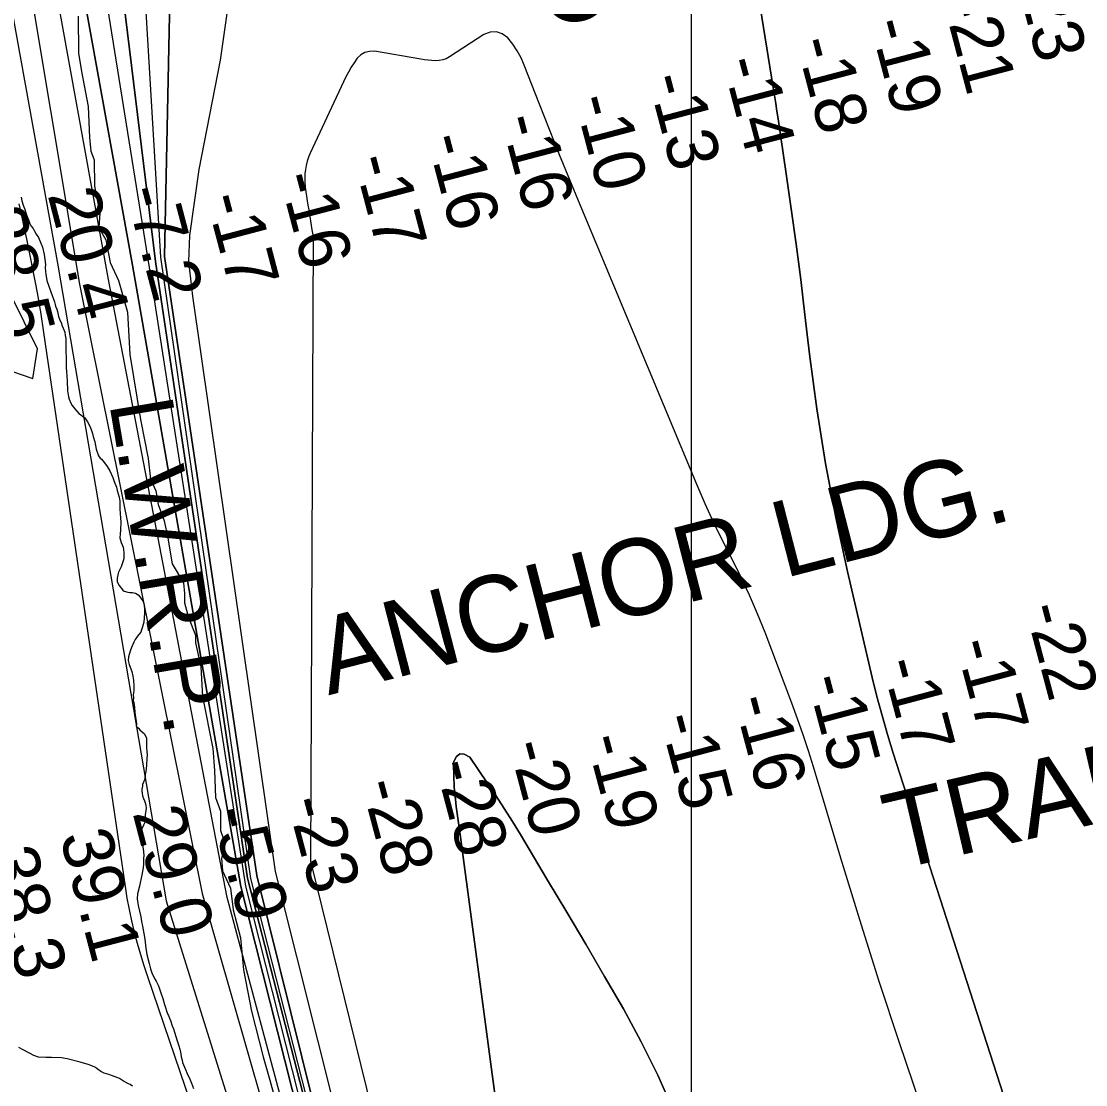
# Model space of a CAD drawing. Extents: x 3250478 to 3288318, y 788638 to 816472.
# Drawn here: x 3274716 to 3276111, y 797415 to 798809 of the extents above; entities that cross this region are included whole.
import ezdxf

# ---------------------------------------------------------------- set-up
doc = ezdxf.new("R2010")
doc.units = 0
for name, color, linetype in [('V-BORW-LINE', 7, 'Continuous'), ('V-CHAN-NAID', 7, 'Continuous'), ('V-GRID-MAJR', 7, 'Continuous'), ('V-RIVR-EDGE', 7, 'Continuous'), ('V-RIVR-RANG', 7, 'Continuous'), ('V-SITE-VEGE', 7, 'Continuous'), ('V-TOPO-DPTH', 7, 'Continuous'), ('V-TOPO-GNAM-IDEN', 7, 'Continuous'), ('V-TOPO-MAJR', 7, 'Continuous'), ('V-TOPO-MINR', 7, 'Continuous'), ('V-TOPO-WATR', 7, 'Continuous'), ('V-TOPO-WATR-IDEN', 7, 'Continuous')]:
    doc.layers.add(name, color=color, linetype=linetype)

msp = doc.modelspace()

# ---------------------------------------------------------------- linework, layer by layer
at = {"layer": 'V-BORW-LINE'}
msp.add_lwpolyline([(3274703.2, 798350.4), (3274731.2, 798340.9), (3274737.2, 798379.6), (3274702.3, 798450.3)], dxfattribs=at)
at = {"layer": 'V-GRID-MAJR'}
msp.add_spline([(3275593.9, 794016.6), (3275594.8, 800075.6), (3275595.7, 806137.8), (3275596.6, 812200), (3275596.6, 812203)], degree=3, dxfattribs=at)
at = {"layer": 'V-RIVR-EDGE'}
msp.add_lwpolyline([(3274790.4, 798816.1), (3274791.1, 798767.4), (3274795, 798743.5), (3274803.5, 798697.4), (3274805.2, 798656.9), (3274806.9, 798638.7), (3274811.6, 798627.4), (3274812, 798593), (3274818.8, 798557.4), (3274817.5, 798538.7), (3274826.6, 798522.6), (3274832.2, 798493), (3274843.4, 798469.1), (3274855, 798427.7), (3274858.4, 798372.1), (3274872.1, 798286.9), (3274882.4, 798236), (3274885.4, 798208.6), (3274892.3, 798193.4), (3274895.3, 798175.5), (3274903, 798154.2), (3274908.2, 798131.6), (3274913.8, 798097.7), (3274928.5, 798072.9), (3274929.8, 798058.9), (3274929.7, 798046.8), (3274935.3, 798027.2), (3274944.4, 798004.1), (3274944.4, 797994.1), (3274951.2, 797962.8), (3274953.3, 797923.7), (3274967.1, 797855.4), (3274969.2, 797826.7), (3274970.4, 797791.1), (3274976.9, 797773.2), (3274977.2, 797748), (3274983.3, 797730.6), (3274978.4, 797711.9), (3274979.7, 797695), (3274990.1, 797672.4), (3274993.5, 797644.1), (3275003.4, 797607.1), (3275007.2, 797565.4), (3275017.5, 797511), (3275033, 797451.4), (3275041.6, 797420.6), (3275047.7, 797398.4)], dxfattribs=at)
at = {"layer": 'V-SITE-VEGE'}
for points in [[(3274715.9, 798578.5), (3274716.6, 798574), (3274718.3, 798568.2), (3274720, 798563.7), (3274722.3, 798556.7), (3274724, 798551.8), (3274725.3, 798548.8), (3274726.7, 798544.9), (3274728.9, 798540.7), (3274731.5, 798537.4), (3274732.8, 798534.7), (3274735.4, 798530.2), (3274738.3, 798525.6)], [(3274738.3, 798525.6), (3274741.5, 798518.4), (3274743.8, 798513), (3274746, 798503.2), (3274747.6, 798490.4), (3274747.4, 798486.4), (3274747.5, 798481.3), (3274748, 798477.6), (3274749.4, 798469.4), (3274754.5, 798454.5), (3274759.5, 798441.2), (3274760.2, 798437.9), (3274760.8, 798435.8), (3274762.5, 798431.8), (3274763.5, 798428.5), (3274764.6, 798422.1), (3274765.9, 798418.5), (3274768.6, 798413), (3274769.2, 798410.6), (3274770.6, 798407), (3274773.2, 798401.6), (3274773.6, 798397.3), (3274774.4, 798393.3), (3274774.1, 798380.2), (3274774.6, 798364.6), (3274774.6, 798355.1), (3274775.1, 798349.6), (3274775.8, 798344.1), (3274776, 798337.1), (3274776.4, 798324.8), (3274777.1, 798321.8), (3274777.6, 798316.9), (3274778.6, 798313.6), (3274780.9, 798308.5), (3274782.8, 798305.5), (3274786.3, 798301), (3274791.4, 798295), (3274793.6, 798293.8), (3274796.7, 798290.9), (3274799.2, 798289.1), (3274802.7, 798284), (3274805.9, 798278.3), (3274807.6, 798274.1), (3274809.3, 798268.6), (3274810.3, 798264.7), (3274812.1, 798257.7), (3274813.1, 798252.8), (3274814.2, 798248.3), (3274817.2, 798239.5), (3274819.4, 798236.5), (3274821, 798235), (3274823.6, 798232), (3274828.3, 798225.4), (3274831.9, 798219.7), (3274835.8, 798211), (3274837.8, 798205.8), (3274840.5, 798198.3), (3274841.5, 798193.7), (3274844.2, 798185.2), (3274845, 798180), (3274845.3, 798169.3), (3274845.5, 798164.1), (3274846, 798157.4), (3274846.4, 798153.2), (3274845.8, 798142.1), (3274845.4, 798137.2), (3274845.2, 798132), (3274846.9, 798125.9), (3274849.3, 798119.6), (3274850.4, 798112.6), (3274850.5, 798108.9), (3274850.3, 798104.9), (3274849.5, 798101.5), (3274846.7, 798093.8), (3274843.5, 798087), (3274842.4, 798083.3), (3274841.6, 798079), (3274841.7, 798074.4), (3274842.4, 798072.3), (3274844, 798069.5), (3274848.8, 798063), (3274850.7, 798061.8), (3274855.6, 798060.7), (3274858.1, 798060.2), (3274861.5, 798060), (3274863.6, 798059.7), (3274865.8, 798059.2), (3274868.9, 798057.1), (3274871.7, 798054.2), (3274875.6, 798048.2), (3274876.9, 798043.9), (3274877.4, 798037.2), (3274877.6, 798032.9), (3274876.4, 798021.3), (3274875.6, 798018.2), (3274874.7, 798015.1), (3274873.6, 798011.4), (3274872.5, 798008.3), (3274870.1, 798004.9), (3274868.1, 798003), (3274865.4, 797998.6)], [(3274865.4, 797998.6), (3274863.4, 797994.9), (3274860.2, 797988), (3274858.6, 797983.1), (3274856.3, 797975.7), (3274856.2, 797971.1), (3274857.2, 797965.9), (3274860.6, 797956.5), (3274862.3, 797950.5), (3274862.8, 797944.7), (3274863.3, 797937.9), (3274863.5, 797931.2), (3274862.7, 797926), (3274862.8, 797922.3), (3274862.6, 797918.3), (3274863.6, 797915.9), (3274864.4, 797909.2), (3274864.9, 797902.8), (3274866.9, 797887.9), (3274866.7, 797884.8), (3274869.5, 797882.1), (3274871.4, 797880.1), (3274874.6, 797877.1), (3274877.4, 797875), (3274880, 797869), (3274880.2, 797864.4), (3274880.1, 797856.8), (3274880.6, 797851.6), (3274880.7, 797847), (3274880.5, 797842.4), (3274879.9, 797833.8), (3274879.7, 797828.9), (3274879.2, 797825.5), (3274878.4, 797821.5), (3274878, 797815.4), (3274874.8, 797808.2), (3274874.6, 797806.1), (3274873.8, 797802.4), (3274874.1, 797800), (3274874.2, 797796.9), (3274875, 797793.3), (3274876, 797789.9), (3274877.3, 797786.9), (3274878.9, 797783), (3274879.3, 797780.8), (3274879.4, 797777.5), (3274879.2, 797774.1), (3274878.5, 797768.6), (3274878.3, 797764), (3274878.4, 797759.4), (3274876.1, 797755), (3274874.7, 797751.9), (3274872.6, 797748.2), (3274873.4, 797743.9), (3274873.5, 797740), (3274874.7, 797729.6), (3274875.4, 797726.6), (3274876.2, 797720.5), (3274876.4, 797715), (3274876.2, 797711.9), (3274876.1, 797704.6), (3274875.6, 797699), (3274874.1, 797690.1), (3274870.9, 797675), (3274868.4, 797665.2), (3274868, 797658.4), (3274868.9, 797649.6), (3274872.7, 797635), (3274873.5, 797628.9), (3274874.6, 797622.8), (3274876.4, 797612.8), (3274877.8, 797605.5), (3274879.1, 797593.9), (3274880.3, 797585.4), (3274883.4, 797573.8), (3274885.4, 797566.5), (3274887.1, 797561.4), (3274890.4, 797554.1), (3274892.6, 797550.5), (3274895.2, 797545.4), (3274896.6, 797541.8), (3274899.3, 797533.9), (3274901.6, 797527.6), (3274903.7, 797520), (3274907.7, 797507.5), (3274909, 797505.4), (3274910, 797502.1), (3274911.3, 797498.8), (3274913.7, 797491.8), (3274915.3, 797487.9), (3274916.7, 797483.6), (3274920.4, 797472.4), (3274922.4, 797465.5), (3274923.8, 797461.2), (3274925.2, 797455.1), (3274925.6, 797451.2), (3274926.7, 797446.9), (3274927.1, 797443.9), (3274930, 797437.8), (3274931, 797434.8), (3274933.3, 797429.4)], [(3274861.6, 797412.8), (3274858.5, 797414.9), (3274856.6, 797415.7), (3274850.1, 797419.2), (3274844.8, 797422.7), (3274842.3, 797423.6), (3274835.5, 797426.4), (3274830.5, 797428.1), (3274824.4, 797429.8), (3274820.3, 797431.8), (3274815.3, 797435.3), (3274813.4, 797437.1), (3274808.2, 797439.4), (3274803.5, 797441.1), (3274793.3, 797444.4), (3274776.1, 797448.5), (3274768.7, 797449.8), (3274755.5, 797450.3), (3274748.2, 797450.4), (3274738.4, 797450.8), (3274732.5, 797453), (3274726.6, 797455.9), (3274717.6, 797460.8), (3274712.9, 797463.5)], [(3274933.3, 797429.4), (3274937.2, 797420.9), (3274938.9, 797416.7), (3274941.8, 797409.7)]]:
    msp.add_lwpolyline(points, dxfattribs=at)
at = {"layer": 'V-TOPO-DPTH'}
for points in [[(3275320.7, 796729.2), (3275299.6, 796772.4), (3275248, 796842.5), (3275216.1, 796884.8), (3275081.1, 797418.9), (3275012.4, 797685.4), (3274892, 798494.3), (3274803.2, 799219.5)], [(3274803.2, 799219.5), (3274892, 798494.3), (3275012.4, 797685.4), (3275081.1, 797418.9), (3275216.1, 796884.8), (3275248, 796842.5), (3275299.6, 796772.4), (3275320.7, 796729.2)], [(3275360.9, 796759.7), (3275343.1, 796787), (3275321.3, 796804.6), (3275285.9, 796832.9), (3275225.3, 796888.9), (3275221.2, 796893.6), (3275201.7, 796975.5), (3275024.8, 797689.1), (3274903.6, 798500.7), (3274917.8, 799176.2)], [(3274917.8, 799176.2), (3274903.6, 798500.7), (3275024.8, 797689.1), (3275201.7, 796975.5), (3275221.2, 796893.6), (3275225.3, 796888.9), (3275285.9, 796832.9), (3275321.3, 796804.6), (3275343.1, 796787), (3275360.9, 796759.7)], [(3275629.2, 799170.6), (3275701.6, 798722.2), (3275703.3, 798711.9), (3275704.9, 798701.6), (3275706.5, 798691.4), (3275708, 798681.1), (3275718.7, 798609.3), (3275725.3, 798563.1), (3275731.7, 798516.8), (3275737.6, 798470.5), (3275743.2, 798424.2), (3275749.1, 798372.8), (3275758.7, 798301), (3275769.9, 798229.4), (3275783.6, 798158.3), (3275798.9, 798087.5), (3275831.4, 797948.6), (3275837.6, 797923.6), (3275844.2, 797898.7), (3275851.4, 797874), (3275859, 797849.4), (3276091.2, 797128.7)], [(3276091.2, 797128.7), (3275859, 797849.4), (3275851.4, 797874), (3275844.2, 797898.7), (3275837.6, 797923.6), (3275831.4, 797948.6), (3275798.9, 798087.5), (3275783.6, 798158.3), (3275769.9, 798229.4), (3275758.7, 798301), (3275749.1, 798372.8), (3275743.2, 798424.2), (3275737.6, 798470.5), (3275731.7, 798516.8), (3275725.3, 798563.1), (3275718.7, 798609.3), (3275708, 798681.1), (3275706.5, 798691.4), (3275704.9, 798701.6), (3275703.3, 798711.9), (3275701.6, 798722.2), (3275629.2, 799170.6)], [(3275270.1, 796729.6), (3275205.7, 796875.8), (3275003.6, 797674.8), (3274861.6, 798489.6), (3274742.1, 799152.7)], [(3275894.3, 797389.7), (3275867, 797469.8), (3275840.4, 797550.1), (3275814.9, 797630.8), (3275790.1, 797711.7), (3275754.3, 797831.5), (3275747.8, 797852.6), (3275740.9, 797873.6), (3275733.6, 797894.4), (3275726, 797915.2), (3275691, 798007.6), (3275681.1, 798032.3), (3275670.6, 798056.7), (3275659.2, 798080.8), (3275647.2, 798104.6), (3275635.2, 798128.3), (3275623.5, 798152.3), (3275612.5, 798176.5), (3275601.9, 798200.9), (3275448.4, 798568.5), (3275434.8, 798601.4), (3275421.4, 798634.3), (3275408.2, 798667.3), (3275395.2, 798700.4), (3275375.3, 798751.8), (3275371, 798761.4), (3275366, 798770.6), (3275360.2, 798779.2), (3275353.7, 798787.5), (3275346.4, 798792.7), (3275338.8, 798795.6), (3275330.6, 798794.9), (3275322.2, 798791.9), (3275277.1, 798762.5), (3275272.9, 798760.2), (3275268.5, 798758.6), (3275263.8, 798757.7), (3275259, 798757.4), (3275254.1, 798757.7), (3275249.2, 798758.1), (3275244.3, 798758.7), (3275239.5, 798759.5), (3275179, 798769.9), (3275172.4, 798769.8), (3275166.3, 798768.5), (3275161, 798765.3), (3275156.2, 798760.8), (3275152.1, 798754.9), (3275148.2, 798748.9), (3275144.7, 798742.6), (3275141.5, 798736.2), (3275094.6, 798636.1), (3275092.4, 798630.9), (3275090.6, 798625.7), (3275089.3, 798620.2), (3275088.3, 798614.7), (3275087.7, 798609.1), (3275087.5, 798603.6), (3275087.7, 798598), (3275088.1, 798592.4), (3275088.2, 798591.6), (3275089, 798585.7), (3275089.8, 798579.7), (3275090.7, 798573.8), (3275091.7, 798567.9), (3275092.7, 798562.1), (3275094.1, 798553.3), (3275095.5, 798544.5), (3275096.9, 798535.7), (3275098.3, 798526.9), (3275095.1, 797707.7), (3275263.8, 797023)], [(3275894.3, 797389.7), (3275867, 797469.8), (3275840.4, 797550.1), (3275814.9, 797630.8), (3275790.1, 797711.7), (3275754.3, 797831.5), (3275747.8, 797852.6), (3275740.9, 797873.6), (3275733.6, 797894.4), (3275726, 797915.2), (3275691, 798007.6), (3275681.1, 798032.3), (3275670.6, 798056.7), (3275659.2, 798080.8), (3275647.2, 798104.6), (3275635.2, 798128.3), (3275623.5, 798152.3), (3275612.5, 798176.5), (3275601.9, 798200.9), (3275448.4, 798568.5), (3275434.8, 798601.4), (3275421.4, 798634.3), (3275408.2, 798667.3), (3275395.2, 798700.4), (3275375.3, 798751.8), (3275371, 798761.4), (3275366, 798770.6), (3275360.2, 798779.2), (3275353.7, 798787.5), (3275346.4, 798792.7), (3275338.8, 798795.6), (3275330.6, 798794.9), (3275322.2, 798791.9), (3275277.1, 798762.5), (3275272.9, 798760.2), (3275268.5, 798758.6), (3275263.8, 798757.7), (3275259, 798757.4), (3275254.1, 798757.7), (3275249.2, 798758.1), (3275244.3, 798758.7), (3275239.5, 798759.5), (3275179, 798769.9), (3275172.4, 798769.8), (3275166.3, 798768.5), (3275161, 798765.3), (3275156.2, 798760.8), (3275152.1, 798754.9), (3275148.2, 798748.9), (3275144.7, 798742.6), (3275141.5, 798736.2), (3275094.6, 798636.1), (3275092.4, 798630.9), (3275090.6, 798625.7), (3275089.3, 798620.2), (3275088.3, 798614.7), (3275087.7, 798609.1), (3275087.5, 798603.6), (3275087.7, 798598), (3275088.1, 798592.4), (3275088.2, 798591.6), (3275089, 798585.7), (3275089.8, 798579.7), (3275090.7, 798573.8), (3275091.7, 798567.9), (3275092.7, 798562.1), (3275094.1, 798553.3), (3275095.5, 798544.5), (3275096.9, 798535.7), (3275098.3, 798526.9), (3275095.1, 797707.7), (3275263.8, 797023)], [(3275392.5, 796983.5), (3275291.2, 797742.6), (3275289.9, 797751.9), (3275288.7, 797761.2), (3275287.4, 797770.4), (3275286.1, 797779.7), (3275285, 797789), (3275284, 797798.3), (3275283.4, 797807.6), (3275283.1, 797816.9), (3275282.6, 797837.4), (3275286.1, 797844.6), (3275290.6, 797848.7), (3275296.6, 797848), (3275303.7, 797844.2), (3275326.8, 797810.5), (3275338, 797793.8), (3275348.9, 797777), (3275359.6, 797760), (3275370.1, 797742.9), (3275405.9, 797683.1), (3275431, 797641), (3275455.9, 797598.8), (3275480.6, 797556.5), (3275505.1, 797514), (3275528.4, 797471), (3275550.2, 797427.3), (3275569.9, 797382.5)], [(3275569.9, 797382.5), (3275550.2, 797427.3), (3275528.4, 797471), (3275505.1, 797514), (3275480.6, 797556.5), (3275455.9, 797598.8), (3275431, 797641), (3275405.9, 797683.1), (3275370.1, 797742.9), (3275359.6, 797760), (3275348.9, 797777), (3275338, 797793.8), (3275326.8, 797810.5), (3275303.7, 797844.2), (3275296.6, 797848), (3275290.6, 797848.7), (3275286.1, 797844.6), (3275282.6, 797837.4), (3275283.1, 797816.9), (3275283.4, 797807.6), (3275284, 797798.3), (3275285, 797789), (3275286.1, 797779.7), (3275287.4, 797770.4), (3275288.7, 797761.2), (3275289.9, 797751.9), (3275291.2, 797742.6), (3275392.5, 796983.5)]]:
    msp.add_lwpolyline(points, dxfattribs=at)
at = {"layer": 'V-TOPO-MAJR'}
msp.add_lwpolyline([(3274650.9, 799170.7), (3274703.8, 798821.2), (3274763.8, 798489.6), (3274905.8, 797655.9), (3275202.8, 796703.7)], dxfattribs=at)
at = {"layer": 'V-TOPO-MINR'}
for points in [[(3274856, 799209.7), (3274898.3, 798500), (3275016.3, 797685.3), (3275218.2, 796893), (3275224.1, 796883.6), (3275258.3, 796844.7), (3275285.9, 796815.8), (3275312.4, 796792.3), (3275324.8, 796774), (3275331.3, 796763.4), (3275338.4, 796751.6)], [(3275360.9, 796759.7), (3275343.1, 796787), (3275321.3, 796804.6), (3275285.9, 796832.9), (3275225.3, 796888.9), (3275221.2, 796893.6), (3275201.7, 796975.5), (3275024.8, 797689.1), (3274903.6, 798500.7), (3274917.8, 799176.2)], [(3275036.8, 799181.6), (3274976.4, 798758.3), (3274948.6, 798615), (3274936.2, 798528.3), (3274935.2, 798494.3), (3274940.4, 798448.9), (3275048.6, 797694.4), (3275243, 796919.1), (3275255.6, 796897.5), (3275289.9, 796868.6), (3275320.5, 796843.3), (3275354.8, 796816.3), (3275372.8, 796789.2), (3275383.7, 796766.6)], [(3274775.8, 799159.5), (3274883.7, 798486.4), (3275010, 797674.9), (3275210.9, 796880.7), (3275298.1, 796721.6)], [(3275629.2, 799170.6), (3275701.6, 798722.2), (3275703.3, 798711.9), (3275704.9, 798701.6), (3275706.5, 798691.4), (3275708, 798681.1), (3275718.7, 798609.3), (3275725.3, 798563.1), (3275731.7, 798516.8), (3275737.6, 798470.5), (3275743.2, 798424.2), (3275749.1, 798372.8), (3275758.7, 798301), (3275769.9, 798229.4), (3275783.6, 798158.3), (3275798.9, 798087.5), (3275831.4, 797948.6), (3275837.6, 797923.6), (3275844.2, 797898.7), (3275851.4, 797874), (3275859, 797849.4), (3276091.2, 797128.7)], [(3274678, 799145.7), (3274792.2, 798464.3), (3274953.1, 797665.3), (3275230, 796698.5)], [(3274706.5, 799151.5), (3274830, 798470.6), (3274984.7, 797662.2), (3275196.2, 796872.7), (3275244.9, 796729.1)], [(3274742.1, 799152.7), (3274861.6, 798489.6), (3275003.6, 797674.8), (3275205.7, 796875.8), (3275270.1, 796729.6)], [(3275894.3, 797389.7), (3275867, 797469.8), (3275840.4, 797550.1), (3275814.9, 797630.8), (3275790.1, 797711.7), (3275754.3, 797831.5), (3275747.8, 797852.6), (3275740.9, 797873.6), (3275733.6, 797894.4), (3275726, 797915.2), (3275691, 798007.6), (3275681.1, 798032.3), (3275670.6, 798056.7), (3275659.2, 798080.8), (3275647.2, 798104.6), (3275635.2, 798128.3), (3275623.5, 798152.3), (3275612.5, 798176.5), (3275601.9, 798200.9), (3275448.4, 798568.5), (3275434.8, 798601.4), (3275421.4, 798634.3), (3275408.2, 798667.3), (3275395.2, 798700.4), (3275375.3, 798751.8), (3275371, 798761.4), (3275366, 798770.6), (3275360.2, 798779.2), (3275353.7, 798787.5), (3275346.4, 798792.7), (3275338.8, 798795.6), (3275330.6, 798794.9), (3275322.2, 798791.9), (3275277.1, 798762.5), (3275272.9, 798760.2), (3275268.5, 798758.6), (3275263.8, 798757.7), (3275259, 798757.4), (3275254.1, 798757.7), (3275249.2, 798758.1), (3275244.3, 798758.7), (3275239.5, 798759.5), (3275179, 798769.9), (3275172.4, 798769.8), (3275166.3, 798768.5), (3275161, 798765.3), (3275156.2, 798760.8), (3275152.1, 798754.9), (3275148.2, 798748.9), (3275144.7, 798742.6), (3275141.5, 798736.2), (3275094.6, 798636.1), (3275092.4, 798630.9), (3275090.6, 798625.7), (3275089.3, 798620.2), (3275088.3, 798614.7), (3275087.7, 798609.1), (3275087.5, 798603.6), (3275087.7, 798598), (3275088.1, 798592.4), (3275088.2, 798591.6), (3275089, 798585.7), (3275089.8, 798579.7), (3275090.7, 798573.8), (3275091.7, 798567.9), (3275092.7, 798562.1), (3275094.1, 798553.3), (3275095.5, 798544.5), (3275096.9, 798535.7), (3275098.3, 798526.9), (3275095.1, 797707.7), (3275263.8, 797023)], [(3274712.7, 798570), (3274716.1, 798554.6), (3274719.4, 798539.3), (3274722.6, 798523.9), (3274725.7, 798508.6), (3274732.8, 798473.3), (3274734.6, 798464.4), (3274736.3, 798455.4), (3274737.9, 798446.3), (3274739.5, 798437.3), (3274741, 798428.3), (3274742.5, 798419.2), (3274743.9, 798410.2), (3274745.2, 798401.1), (3274851.9, 797674.5), (3274854.3, 797659.5), (3274857.1, 797644.5), (3274860.3, 797629.6), (3274863.9, 797614.8), (3274867.9, 797600.1), (3274872.1, 797585.4), (3274876.6, 797570.9), (3274881.3, 797556.4), (3275015.7, 797162.4)], [(3275569.9, 797382.5), (3275550.2, 797427.3), (3275528.4, 797471), (3275505.1, 797514), (3275480.6, 797556.5), (3275455.9, 797598.8), (3275431, 797641), (3275405.9, 797683.1), (3275370.1, 797742.9), (3275359.6, 797760), (3275348.9, 797777), (3275338, 797793.8), (3275326.8, 797810.5), (3275303.7, 797844.2), (3275296.6, 797848), (3275290.6, 797848.7), (3275286.1, 797844.6), (3275282.6, 797837.4), (3275283.1, 797816.9), (3275283.4, 797807.6), (3275284, 797798.3), (3275285, 797789), (3275286.1, 797779.7), (3275287.4, 797770.4), (3275288.7, 797761.2), (3275289.9, 797751.9), (3275291.2, 797742.6), (3275392.5, 796983.5)]]:
    msp.add_lwpolyline(points, dxfattribs=at)
at = {"layer": 'V-TOPO-WATR'}
msp.add_lwpolyline([(3275320.7, 796729.2), (3275299.6, 796772.4), (3275248, 796842.5), (3275216.1, 796884.8), (3275081.1, 797418.9), (3275012.4, 797685.4), (3274892, 798494.3), (3274803.2, 799219.5)], dxfattribs=at)

# ---------------------------------------------------------------- texts
at = {"layer": 'V-CHAN-NAID'}
for s, rotation, p in [('CROWN VANTAGE OUTFLOW (260.1)', 13.712, (3275402.3, 798798.9)), ('TRANSMONTAIGNE (259.9) (2)', 13.0616, (3275861.2, 797695.7))]:
    msp.add_text(s, height=100, rotation=rotation, dxfattribs=at).set_placement(p)
at = {"layer": 'V-RIVR-RANG'}
for s, rotation, p in [('-23', 284.7584, (3276016.3, 798876.9)), ('-21', 284.7584, (3275923.9, 798835.1)), ('-19', 284.7584, (3275828, 798806.8)), ('-18', 284.7584, (3275731, 798782.3)), ('-14', 284.7584, (3275634.4, 798756.3)), ('-13', 284.7584, (3275536.8, 798734.4)), ('-10', 284.7584, (3275440.6, 798706.8)), ('-16', 284.7584, (3275344.1, 798680.8)), ('-16', 284.7584, (3275247.3, 798655.6)), ('-17', 284.7584, (3275151.2, 798628.1)), ('-16', 284.7584, (3275053.8, 798605.1)), ('20.4', 284.4783, (3274750.2, 798582)), ('-7.2', 284.7584, (3274851.7, 798587.3)), ('-17', 284.7584, (3274957.6, 798577.6)), ('38.5', 284.4783, (3274653.5, 798556.8)), ('-22', 284.8695, (3276031.2, 798039.9)), ('-17', 284.8695, (3275940.1, 797993.3)), ('-17', 284.8695, (3275843.4, 797967.9)), ('-15', 284.8695, (3275745.7, 797946.3)), ('-16', 284.8695, (3275649.4, 797919.3)), ('-15', 284.8695, (3275552.3, 797895.4)), ('-20', 284.8695, (3275354.7, 797860.1)), ('-19', 284.8695, (3275456, 797868.2)), ('-28', 284.8695, (3275258.1, 797834.5)), ('-28', 284.8695, (3275161.3, 797809)), ('29.0', 284.5883, (3274861.6, 797771.3)), ('-23', 284.8695, (3275064, 797786.2)), ('-5.9', 284.8695, (3274964.1, 797772.7)), ('39.1', 284.5883, (3274766.2, 797740.8)), ('38.3', 284.5883, (3274668.9, 797717.7))]:
    msp.add_text(s, height=67, rotation=rotation, dxfattribs=at).set_placement(p)
at = {"layer": 'V-TOPO-GNAM-IDEN'}
msp.add_text('ANCHOR LDG.', height=100, rotation=14.4185, dxfattribs=at).set_placement((3275118.5, 797925.2))
at = {"layer": 'V-TOPO-WATR-IDEN'}
msp.add_text('L.W.R.P.', height=83, rotation=279.656, dxfattribs=at).set_placement((3274831.1, 798308.1))

doc.saveas('drawing.dxf')
